(* Logix 5000 project; controller AMCI_3601_AOP_AOI_Sample_RSLogix_V28 vendor 1 type 14 code 108 rev 28.11; software revision 28.00; part 3 of 4 *)

ADD_ON_INSTRUCTION AMCI_3601_AOP_Program_Blend_Move   (* revision 0.0 *)
// Revision note:
// 3/2020: Version 0 is the initial release
VAR_INPUT
   Status_Bits_MSW : INT; {required}
   Status_Bits_LSW : INT; {required}
        .9   // The 3601 module sets this bit to Acknowledge the receipt of a blend move programming block
   Number_of_Segments : INT; {required}
   Final_Move_Deceleration : INT; {required}
   Acceleration_Type_segments_9_to_16 : INT;
   Acceleration_Type_segments_1_to_8 : INT;
   Segment_1_Distance : DINT; {required}
   Segment_1_Programmed_Speed : DINT; {required}
   Segment_1_Acceleration_Deceleration : INT; {required}
   Segment_2_Distance : DINT; {required}
   Segment_2_Programmed_Speed : DINT; {required}
   Segment_2_Acceleration_Deceleration : INT; {required}
   Segment_3_Distance : DINT; {required}
   Segment_3_Programmed_Speed : DINT; {required}
   Segment_3_Acceleration_Deceleration : INT; {required}
   Segment_4_Distance : DINT; {required}
   Segment_4_Programmed_Speed : DINT; {required}
   Segment_4_Acceleration_Deceleration : INT; {required}
   Segment_5_Distance : DINT; {required}
   Segment_5_Programmed_Speed : DINT; {required}
   Segment_5_Acceleration_Deceleration : INT; {required}
   Segment_6_Distance : DINT; {required}
   Segment_6_Programmed_Speed : DINT; {required}
   Segment_6_Acceleration_Deceleration : INT; {required}
   Segment_7_Distance : DINT; {required}
   Segment_7_Programmed_Speed : DINT; {required}
   Segment_7_Acceleration_Deceleration : INT; {required}
   Segment_8_Distance : DINT; {required}
   Segment_8_Programmed_Speed : DINT; {required}
   Segment_8_Acceleration_Deceleration : INT; {required}
   Segment_9_Distance : DINT; {required}
   Segment_9_Programmed_Speed : DINT; {required}
   Segment_9_Acceleration_Deceleration : INT; {required}
   Segment_10_Distance : DINT; {required}
   Segment_10_Programmed_Speed : DINT; {required}
   Segment_10_Acceleration_Deceleration : INT; {required}
   Segment_11_Distance : DINT; {required}
   Segment_11_Programmed_Speed : DINT; {required}
   Segment_11_Acceleration_Deceleration : INT; {required}
   Segment_12_Distance : DINT; {required}
   Segment_12_Programmed_Speed : DINT; {required}
   Segment_12_Acceleration_Deceleration : INT; {required}
   Segment_13_Distance : DINT; {required}
   Segment_13_Programmed_Speed : DINT; {required}
   Segment_13_Acceleration_Deceleration : INT; {required}
   Segment_14_Distance : DINT; {required}
   Segment_14_Programmed_Speed : DINT; {required}
   Segment_14_Acceleration_Deceleration : INT; {required}
   Segment_15_Distance : DINT; {required}
   Segment_15_Programmed_Speed : DINT; {required}
   Segment_15_Acceleration_Deceleration : INT; {required}
   Segment_16_Distance : DINT; {required}
   Segment_16_Programmed_Speed : DINT; {required}
   Segment_16_Acceleration_Deceleration : INT; {required}
END_VAR
VAR_OUTPUT
   Blend_Move_Programmed : BOOL; {access Read Only, visible}
END_VAR
VAR_IN_OUT
   AMCI_3601_output_data : AM:1769_3601:O:0; {required}
END_VAR
VAR
   command_data_block : INT[8];
   Blend_Move_setup : INT[8] := ([1] := 768);
   Blend_Move_counter : COUNTER;
   Programmed_Speed : DINT;
   Distance : DINT;
   upper_result_X_1000 : DINT;
END_VAR

ROUTINE Logic   (* ladder *)
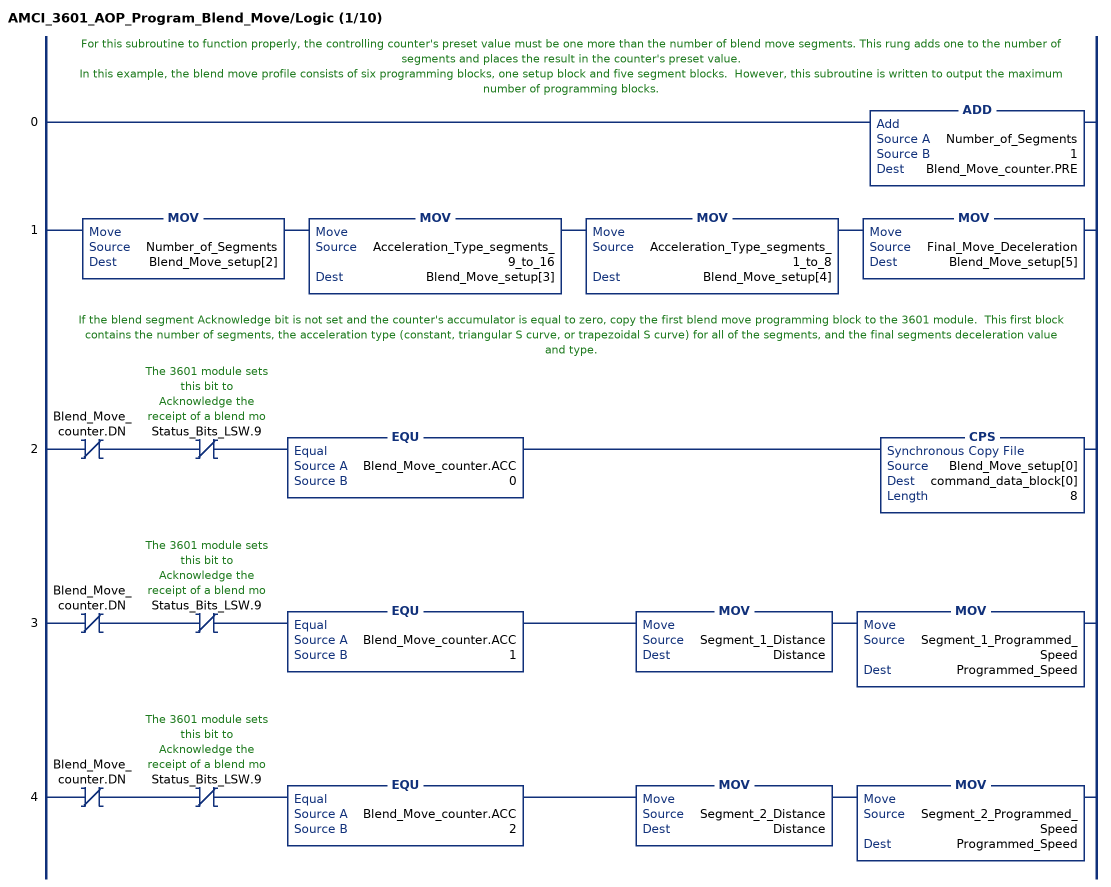
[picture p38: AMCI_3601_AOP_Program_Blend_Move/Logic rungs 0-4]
   // For this subroutine to function properly, the controlling counter's preset value must be one more than the number of blend move segments. This rung adds one to the number of segments and places the result in the counter's preset value.
   // In this example, the blend move profile consists of six programming blocks, one setup block and five segment blocks.  However, this subroutine is written to output the maximum number of programming blocks.
   0: ADD(Number_of_Segments,1,Blend_Move_counter.PRE);
   1: MOV(Number_of_Segments,Blend_Move_setup[2])MOV(Acceleration_Type_segments_9_to_16,Blend_Move_setup[3])MOV(Acceleration_Type_segments_1_to_8,Blend_Move_setup[4])MOV(Final_Move_Deceleration,Blend_Move_setup[5]);
   // If the blend segment Acknowledge bit is not set and the counter's accumulator is equal to zero, copy the first blend move programming block to the 3601 module.  This first block contains the number of segments, the acceleration type (constant, triangular S curve, or trapezoidal S curve) for all of the segments, and the final segments deceleration value and type.
   2: XIO(Blend_Move_counter.DN)XIO(Status_Bits_LSW.9)EQU(Blend_Move_counter.ACC,0)CPS(Blend_Move_setup[0],command_data_block[0],8);
   3: XIO(Blend_Move_counter.DN)XIO(Status_Bits_LSW.9)EQU(Blend_Move_counter.ACC,1)MOV(Segment_1_Distance,Distance)MOV(Segment_1_Programmed_Speed,Programmed_Speed);
   4: XIO(Blend_Move_counter.DN)XIO(Status_Bits_LSW.9)EQU(Blend_Move_counter.ACC,2)MOV(Segment_2_Distance,Distance)MOV(Segment_2_Programmed_Speed,Programmed_Speed);
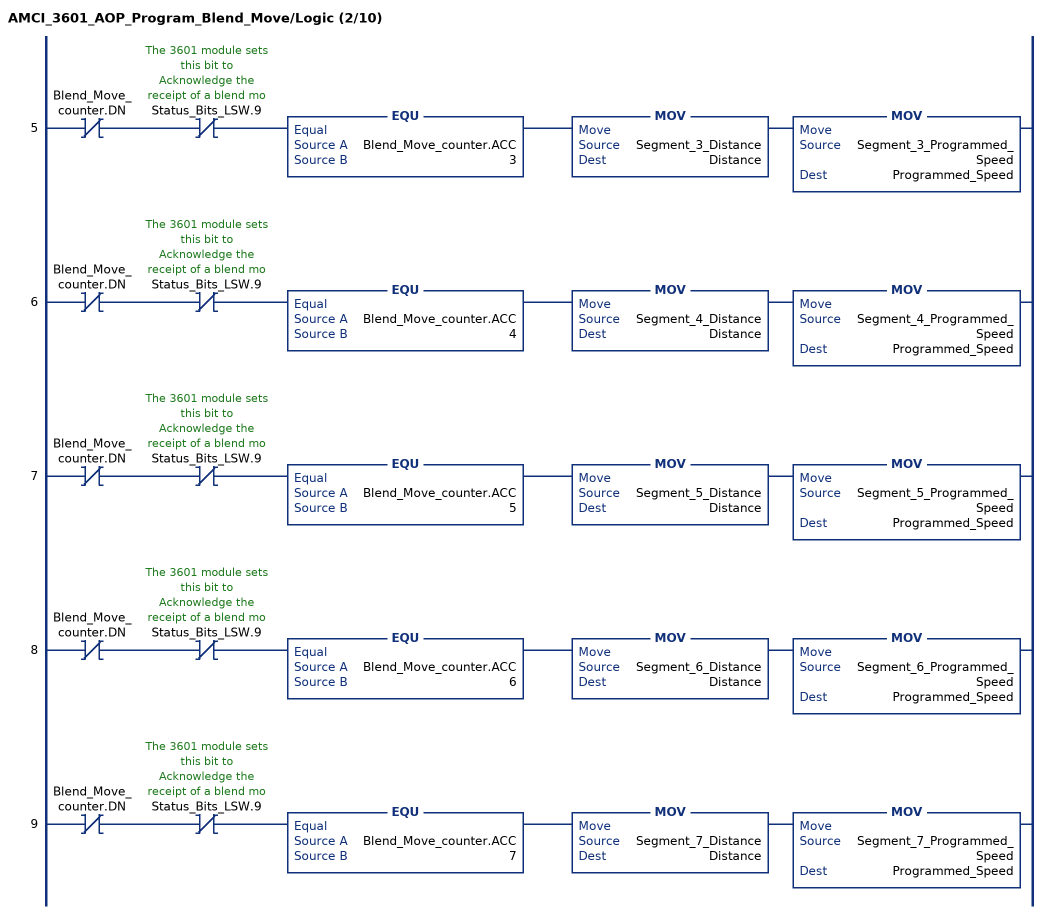
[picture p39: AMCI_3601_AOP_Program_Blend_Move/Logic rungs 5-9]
   5: XIO(Blend_Move_counter.DN)XIO(Status_Bits_LSW.9)EQU(Blend_Move_counter.ACC,3)MOV(Segment_3_Distance,Distance)MOV(Segment_3_Programmed_Speed,Programmed_Speed);
   6: XIO(Blend_Move_counter.DN)XIO(Status_Bits_LSW.9)EQU(Blend_Move_counter.ACC,4)MOV(Segment_4_Distance,Distance)MOV(Segment_4_Programmed_Speed,Programmed_Speed);
   7: XIO(Blend_Move_counter.DN)XIO(Status_Bits_LSW.9)EQU(Blend_Move_counter.ACC,5)MOV(Segment_5_Distance,Distance)MOV(Segment_5_Programmed_Speed,Programmed_Speed);
   8: XIO(Blend_Move_counter.DN)XIO(Status_Bits_LSW.9)EQU(Blend_Move_counter.ACC,6)MOV(Segment_6_Distance,Distance)MOV(Segment_6_Programmed_Speed,Programmed_Speed);
   9: XIO(Blend_Move_counter.DN)XIO(Status_Bits_LSW.9)EQU(Blend_Move_counter.ACC,7)MOV(Segment_7_Distance,Distance)MOV(Segment_7_Programmed_Speed,Programmed_Speed);
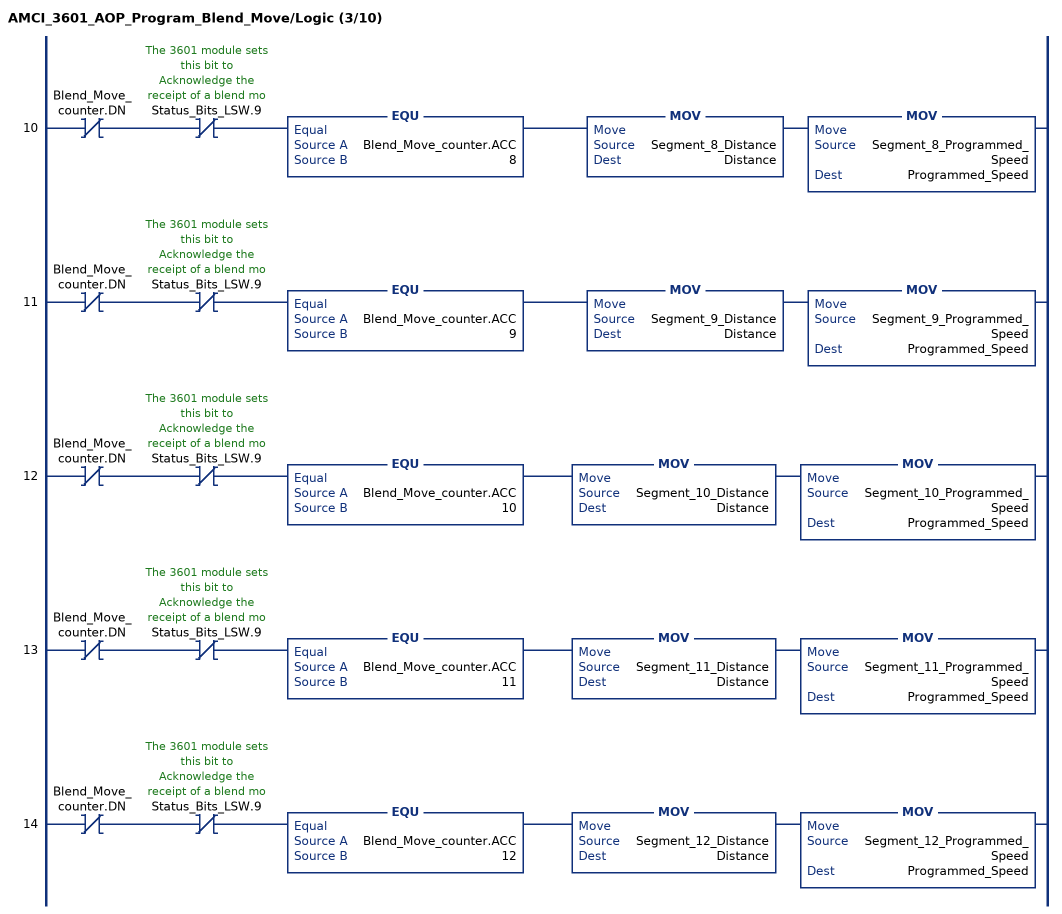
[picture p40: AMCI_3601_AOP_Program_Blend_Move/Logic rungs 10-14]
   10: XIO(Blend_Move_counter.DN)XIO(Status_Bits_LSW.9)EQU(Blend_Move_counter.ACC,8)MOV(Segment_8_Distance,Distance)MOV(Segment_8_Programmed_Speed,Programmed_Speed);
   11: XIO(Blend_Move_counter.DN)XIO(Status_Bits_LSW.9)EQU(Blend_Move_counter.ACC,9)MOV(Segment_9_Distance,Distance)MOV(Segment_9_Programmed_Speed,Programmed_Speed);
   12: XIO(Blend_Move_counter.DN)XIO(Status_Bits_LSW.9)EQU(Blend_Move_counter.ACC,10)MOV(Segment_10_Distance,Distance)MOV(Segment_10_Programmed_Speed,Programmed_Speed);
   13: XIO(Blend_Move_counter.DN)XIO(Status_Bits_LSW.9)EQU(Blend_Move_counter.ACC,11)MOV(Segment_11_Distance,Distance)MOV(Segment_11_Programmed_Speed,Programmed_Speed);
   14: XIO(Blend_Move_counter.DN)XIO(Status_Bits_LSW.9)EQU(Blend_Move_counter.ACC,12)MOV(Segment_12_Distance,Distance)MOV(Segment_12_Programmed_Speed,Programmed_Speed);
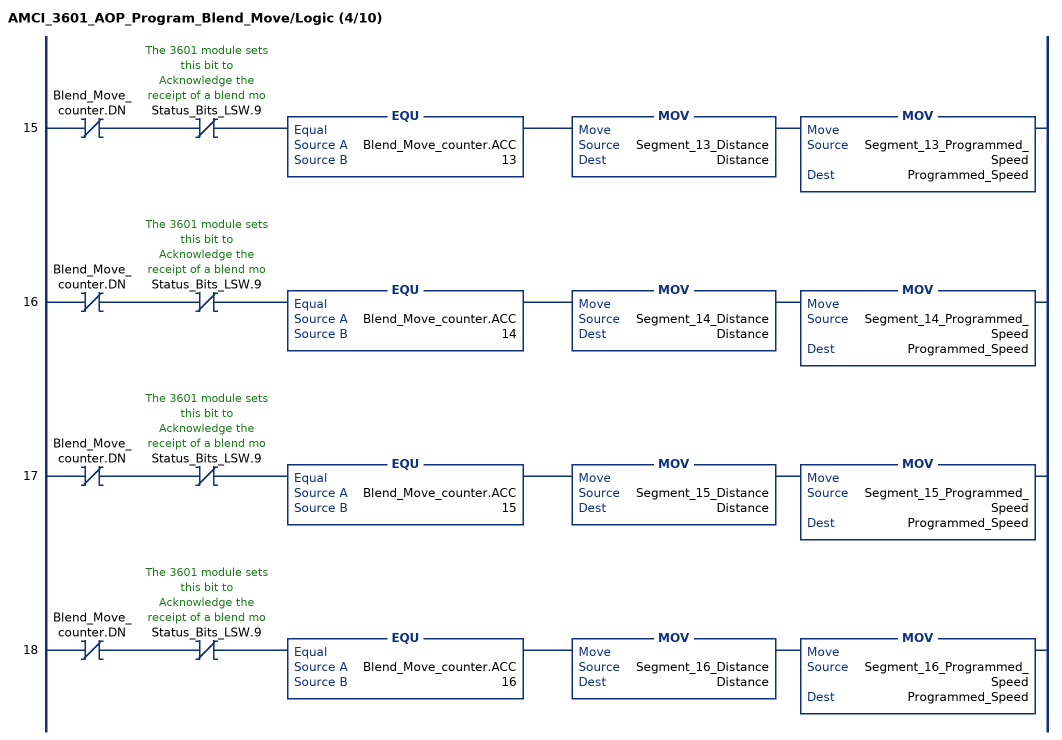
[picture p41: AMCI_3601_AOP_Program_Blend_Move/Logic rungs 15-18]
   15: XIO(Blend_Move_counter.DN)XIO(Status_Bits_LSW.9)EQU(Blend_Move_counter.ACC,13)MOV(Segment_13_Distance,Distance)MOV(Segment_13_Programmed_Speed,Programmed_Speed);
   16: XIO(Blend_Move_counter.DN)XIO(Status_Bits_LSW.9)EQU(Blend_Move_counter.ACC,14)MOV(Segment_14_Distance,Distance)MOV(Segment_14_Programmed_Speed,Programmed_Speed);
   17: XIO(Blend_Move_counter.DN)XIO(Status_Bits_LSW.9)EQU(Blend_Move_counter.ACC,15)MOV(Segment_15_Distance,Distance)MOV(Segment_15_Programmed_Speed,Programmed_Speed);
   18: XIO(Blend_Move_counter.DN)XIO(Status_Bits_LSW.9)EQU(Blend_Move_counter.ACC,16)MOV(Segment_16_Distance,Distance)MOV(Segment_16_Programmed_Speed,Programmed_Speed);
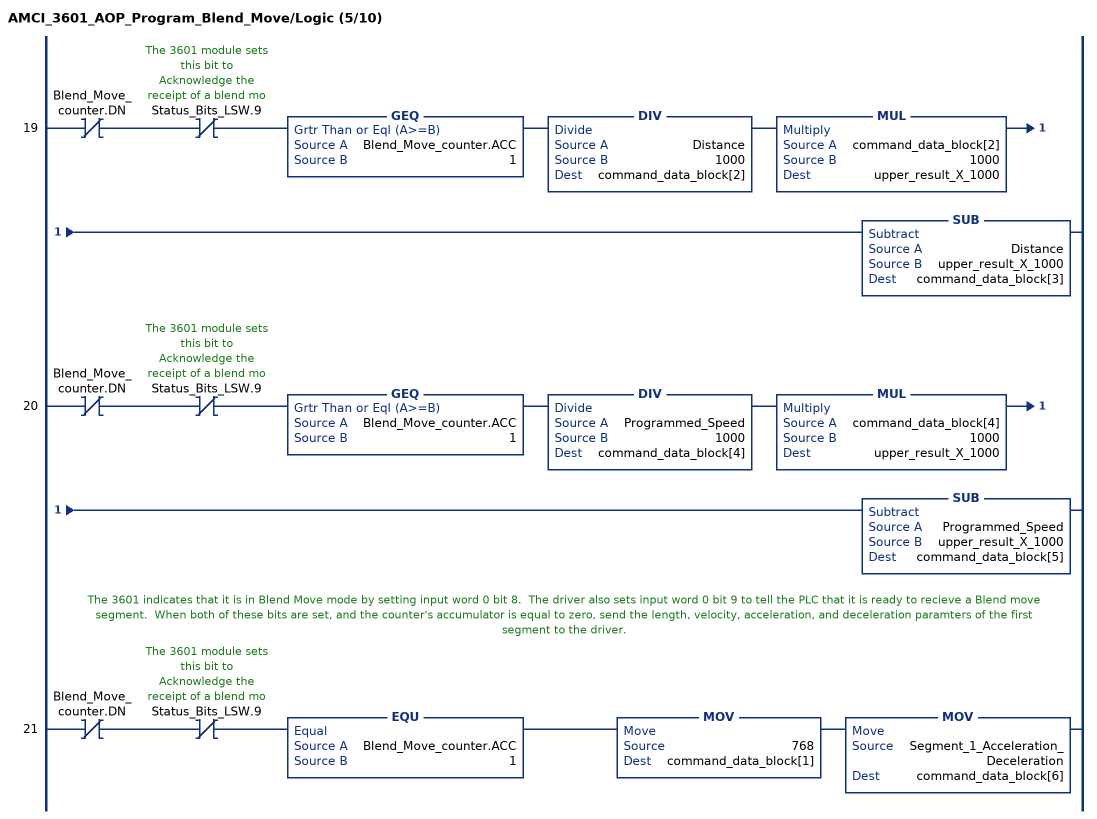
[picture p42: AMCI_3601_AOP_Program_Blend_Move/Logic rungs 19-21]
   19: XIO(Blend_Move_counter.DN)XIO(Status_Bits_LSW.9)GEQ(Blend_Move_counter.ACC,1)DIV(Distance,1000,command_data_block[2])MUL(command_data_block[2],1000,upper_result_X_1000)SUB(Distance,upper_result_X_1000,command_data_block[3]);
   20: XIO(Blend_Move_counter.DN)XIO(Status_Bits_LSW.9)GEQ(Blend_Move_counter.ACC,1)DIV(Programmed_Speed,1000,command_data_block[4])MUL(command_data_block[4],1000,upper_result_X_1000)SUB(Programmed_Speed,upper_result_X_1000,command_data_block[5]);
   // The 3601 indicates that it is in Blend Move mode by setting input word 0 bit 8.  The driver also sets input word 0 bit 9 to tell the PLC that it is ready to recieve a Blend move segment.  When both of these bits are set, and the counter's accumulator is equal to zero, send the length, velocity, acceleration, and deceleration paramters of the first segment to the driver.
   21: XIO(Blend_Move_counter.DN)XIO(Status_Bits_LSW.9)EQU(Blend_Move_counter.ACC,1)MOV(768,command_data_block[1])MOV(Segment_1_Acceleration_Deceleration,command_data_block[6]);
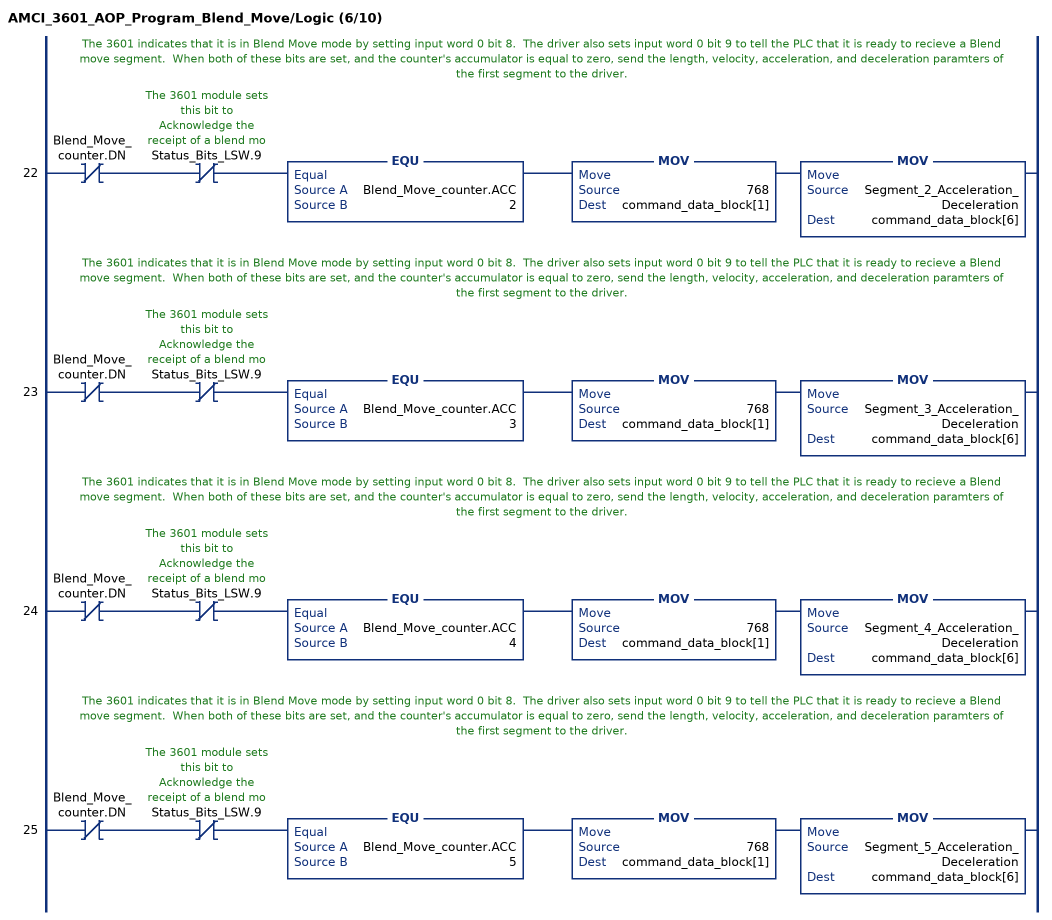
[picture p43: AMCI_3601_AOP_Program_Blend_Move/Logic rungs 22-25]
   // The 3601 indicates that it is in Blend Move mode by setting input word 0 bit 8.  The driver also sets input word 0 bit 9 to tell the PLC that it is ready to recieve a Blend move segment.  When both of these bits are set, and the counter's accumulator is equal to zero, send the length, velocity, acceleration, and deceleration paramters of the first segment to the driver.
   22: XIO(Blend_Move_counter.DN)XIO(Status_Bits_LSW.9)EQU(Blend_Move_counter.ACC,2)MOV(768,command_data_block[1])MOV(Segment_2_Acceleration_Deceleration,command_data_block[6]);
   // The 3601 indicates that it is in Blend Move mode by setting input word 0 bit 8.  The driver also sets input word 0 bit 9 to tell the PLC that it is ready to recieve a Blend move segment.  When both of these bits are set, and the counter's accumulator is equal to zero, send the length, velocity, acceleration, and deceleration paramters of the first segment to the driver.
   23: XIO(Blend_Move_counter.DN)XIO(Status_Bits_LSW.9)EQU(Blend_Move_counter.ACC,3)MOV(768,command_data_block[1])MOV(Segment_3_Acceleration_Deceleration,command_data_block[6]);
   // The 3601 indicates that it is in Blend Move mode by setting input word 0 bit 8.  The driver also sets input word 0 bit 9 to tell the PLC that it is ready to recieve a Blend move segment.  When both of these bits are set, and the counter's accumulator is equal to zero, send the length, velocity, acceleration, and deceleration paramters of the first segment to the driver.
   24: XIO(Blend_Move_counter.DN)XIO(Status_Bits_LSW.9)EQU(Blend_Move_counter.ACC,4)MOV(768,command_data_block[1])MOV(Segment_4_Acceleration_Deceleration,command_data_block[6]);
   // The 3601 indicates that it is in Blend Move mode by setting input word 0 bit 8.  The driver also sets input word 0 bit 9 to tell the PLC that it is ready to recieve a Blend move segment.  When both of these bits are set, and the counter's accumulator is equal to zero, send the length, velocity, acceleration, and deceleration paramters of the first segment to the driver.
   25: XIO(Blend_Move_counter.DN)XIO(Status_Bits_LSW.9)EQU(Blend_Move_counter.ACC,5)MOV(768,command_data_block[1])MOV(Segment_5_Acceleration_Deceleration,command_data_block[6]);
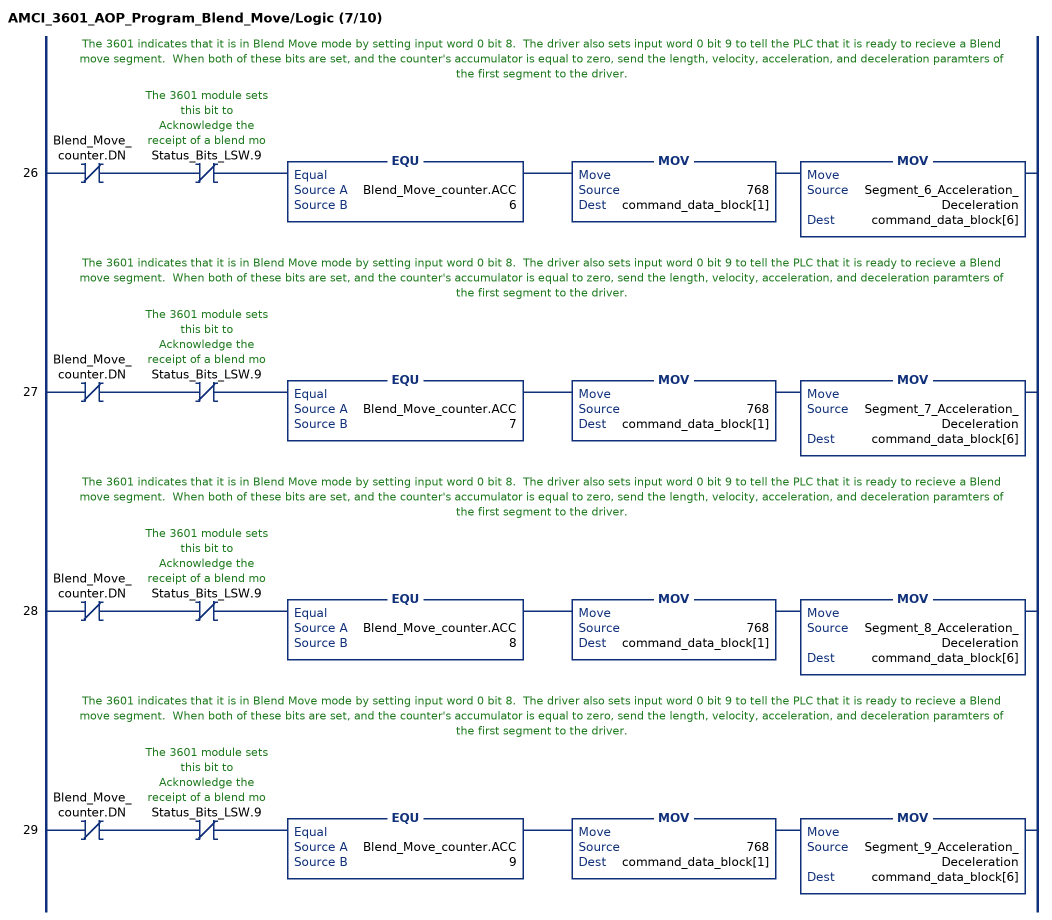
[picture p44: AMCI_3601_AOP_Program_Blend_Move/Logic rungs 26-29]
   // The 3601 indicates that it is in Blend Move mode by setting input word 0 bit 8.  The driver also sets input word 0 bit 9 to tell the PLC that it is ready to recieve a Blend move segment.  When both of these bits are set, and the counter's accumulator is equal to zero, send the length, velocity, acceleration, and deceleration paramters of the first segment to the driver.
   26: XIO(Blend_Move_counter.DN)XIO(Status_Bits_LSW.9)EQU(Blend_Move_counter.ACC,6)MOV(768,command_data_block[1])MOV(Segment_6_Acceleration_Deceleration,command_data_block[6]);
   // The 3601 indicates that it is in Blend Move mode by setting input word 0 bit 8.  The driver also sets input word 0 bit 9 to tell the PLC that it is ready to recieve a Blend move segment.  When both of these bits are set, and the counter's accumulator is equal to zero, send the length, velocity, acceleration, and deceleration paramters of the first segment to the driver.
   27: XIO(Blend_Move_counter.DN)XIO(Status_Bits_LSW.9)EQU(Blend_Move_counter.ACC,7)MOV(768,command_data_block[1])MOV(Segment_7_Acceleration_Deceleration,command_data_block[6]);
   // The 3601 indicates that it is in Blend Move mode by setting input word 0 bit 8.  The driver also sets input word 0 bit 9 to tell the PLC that it is ready to recieve a Blend move segment.  When both of these bits are set, and the counter's accumulator is equal to zero, send the length, velocity, acceleration, and deceleration paramters of the first segment to the driver.
   28: XIO(Blend_Move_counter.DN)XIO(Status_Bits_LSW.9)EQU(Blend_Move_counter.ACC,8)MOV(768,command_data_block[1])MOV(Segment_8_Acceleration_Deceleration,command_data_block[6]);
   // The 3601 indicates that it is in Blend Move mode by setting input word 0 bit 8.  The driver also sets input word 0 bit 9 to tell the PLC that it is ready to recieve a Blend move segment.  When both of these bits are set, and the counter's accumulator is equal to zero, send the length, velocity, acceleration, and deceleration paramters of the first segment to the driver.
   29: XIO(Blend_Move_counter.DN)XIO(Status_Bits_LSW.9)EQU(Blend_Move_counter.ACC,9)MOV(768,command_data_block[1])MOV(Segment_9_Acceleration_Deceleration,command_data_block[6]);
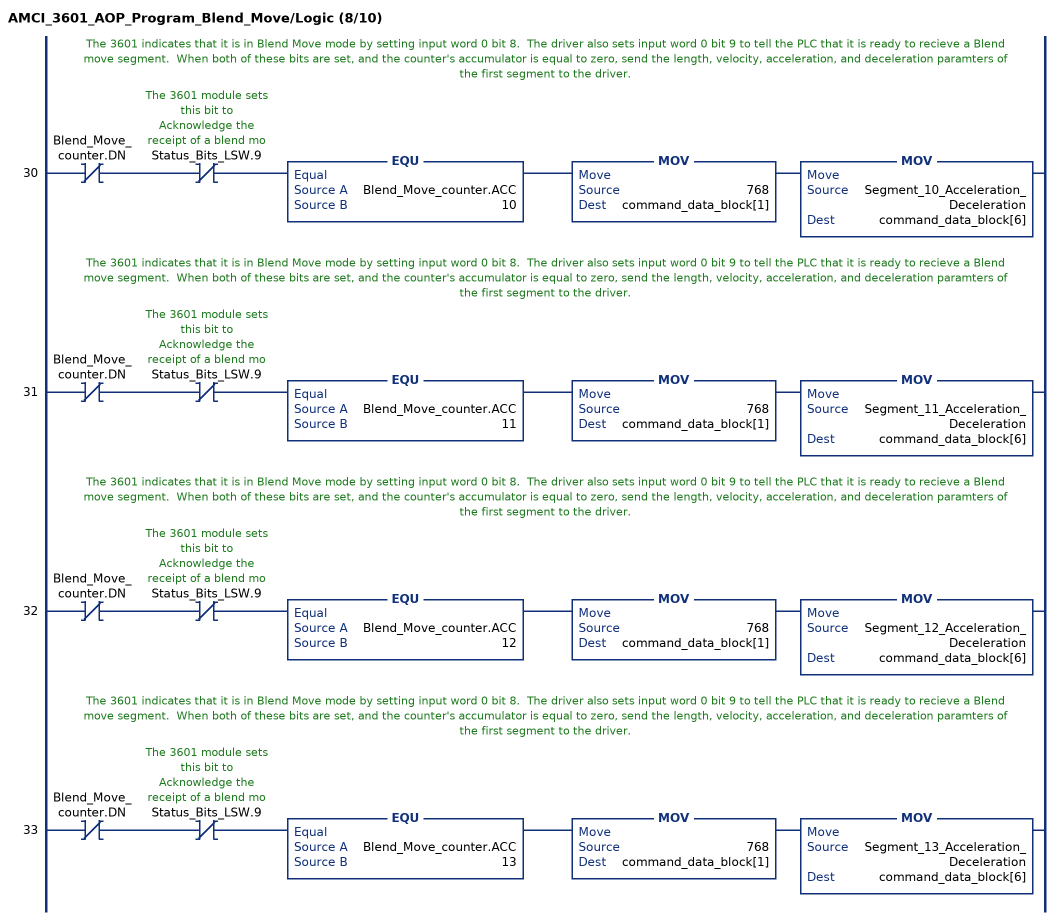
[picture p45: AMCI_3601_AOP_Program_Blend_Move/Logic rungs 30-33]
   // The 3601 indicates that it is in Blend Move mode by setting input word 0 bit 8.  The driver also sets input word 0 bit 9 to tell the PLC that it is ready to recieve a Blend move segment.  When both of these bits are set, and the counter's accumulator is equal to zero, send the length, velocity, acceleration, and deceleration paramters of the first segment to the driver.
   30: XIO(Blend_Move_counter.DN)XIO(Status_Bits_LSW.9)EQU(Blend_Move_counter.ACC,10)MOV(768,command_data_block[1])MOV(Segment_10_Acceleration_Deceleration,command_data_block[6]);
   // The 3601 indicates that it is in Blend Move mode by setting input word 0 bit 8.  The driver also sets input word 0 bit 9 to tell the PLC that it is ready to recieve a Blend move segment.  When both of these bits are set, and the counter's accumulator is equal to zero, send the length, velocity, acceleration, and deceleration paramters of the first segment to the driver.
   31: XIO(Blend_Move_counter.DN)XIO(Status_Bits_LSW.9)EQU(Blend_Move_counter.ACC,11)MOV(768,command_data_block[1])MOV(Segment_11_Acceleration_Deceleration,command_data_block[6]);
   // The 3601 indicates that it is in Blend Move mode by setting input word 0 bit 8.  The driver also sets input word 0 bit 9 to tell the PLC that it is ready to recieve a Blend move segment.  When both of these bits are set, and the counter's accumulator is equal to zero, send the length, velocity, acceleration, and deceleration paramters of the first segment to the driver.
   32: XIO(Blend_Move_counter.DN)XIO(Status_Bits_LSW.9)EQU(Blend_Move_counter.ACC,12)MOV(768,command_data_block[1])MOV(Segment_12_Acceleration_Deceleration,command_data_block[6]);
   // The 3601 indicates that it is in Blend Move mode by setting input word 0 bit 8.  The driver also sets input word 0 bit 9 to tell the PLC that it is ready to recieve a Blend move segment.  When both of these bits are set, and the counter's accumulator is equal to zero, send the length, velocity, acceleration, and deceleration paramters of the first segment to the driver.
   33: XIO(Blend_Move_counter.DN)XIO(Status_Bits_LSW.9)EQU(Blend_Move_counter.ACC,13)MOV(768,command_data_block[1])MOV(Segment_13_Acceleration_Deceleration,command_data_block[6]);
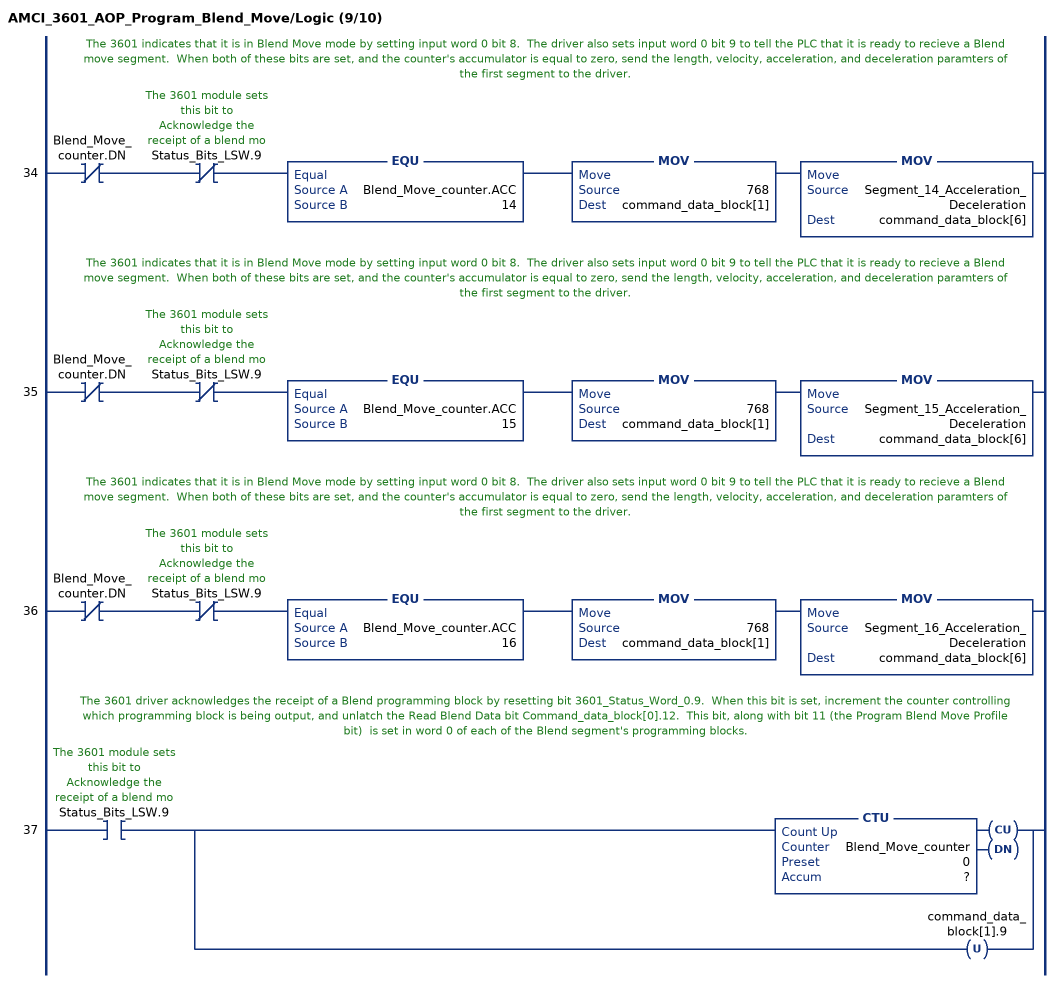
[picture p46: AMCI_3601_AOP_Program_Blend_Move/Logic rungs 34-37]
   // The 3601 indicates that it is in Blend Move mode by setting input word 0 bit 8.  The driver also sets input word 0 bit 9 to tell the PLC that it is ready to recieve a Blend move segment.  When both of these bits are set, and the counter's accumulator is equal to zero, send the length, velocity, acceleration, and deceleration paramters of the first segment to the driver.
   34: XIO(Blend_Move_counter.DN)XIO(Status_Bits_LSW.9)EQU(Blend_Move_counter.ACC,14)MOV(768,command_data_block[1])MOV(Segment_14_Acceleration_Deceleration,command_data_block[6]);
   // The 3601 indicates that it is in Blend Move mode by setting input word 0 bit 8.  The driver also sets input word 0 bit 9 to tell the PLC that it is ready to recieve a Blend move segment.  When both of these bits are set, and the counter's accumulator is equal to zero, send the length, velocity, acceleration, and deceleration paramters of the first segment to the driver.
   35: XIO(Blend_Move_counter.DN)XIO(Status_Bits_LSW.9)EQU(Blend_Move_counter.ACC,15)MOV(768,command_data_block[1])MOV(Segment_15_Acceleration_Deceleration,command_data_block[6]);
   // The 3601 indicates that it is in Blend Move mode by setting input word 0 bit 8.  The driver also sets input word 0 bit 9 to tell the PLC that it is ready to recieve a Blend move segment.  When both of these bits are set, and the counter's accumulator is equal to zero, send the length, velocity, acceleration, and deceleration paramters of the first segment to the driver.
   36: XIO(Blend_Move_counter.DN)XIO(Status_Bits_LSW.9)EQU(Blend_Move_counter.ACC,16)MOV(768,command_data_block[1])MOV(Segment_16_Acceleration_Deceleration,command_data_block[6]);
   // The 3601 driver acknowledges the receipt of a Blend programming block by resetting bit 3601_Status_Word_0.9.  When this bit is set, increment the counter controlling which programming block is being output, and unlatch the Read Blend Data bit Command_data_block[0].12.  This bit, along with bit 11 (the Program Blend Move Profile bit)  is set in word 0 of each of the Blend segment's programming blocks.
   37: XIC(Status_Bits_LSW.9)[CTU(Blend_Move_counter,?,?) ,OTU(command_data_block[1].9) ];
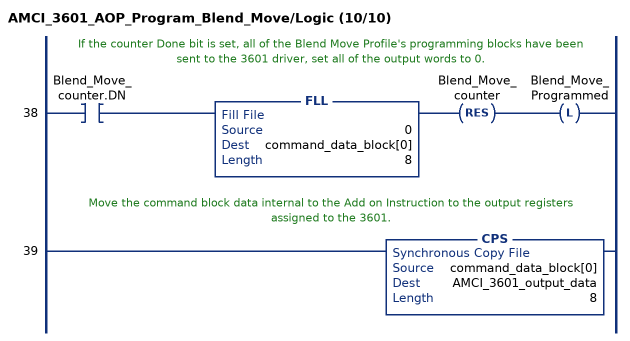
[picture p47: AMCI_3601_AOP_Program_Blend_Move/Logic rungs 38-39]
   // If the counter Done bit is set, all of the Blend Move Profile's programming blocks have been sent to the 3601 driver, set all of the output words to 0.
   38: XIC(Blend_Move_counter.DN)FLL(0,command_data_block[0],8)RES(Blend_Move_counter)OTL(Blend_Move_Programmed);
   // Move the command block data internal to the Add on Instruction to the output registers assigned to the 3601.
   39: CPS(command_data_block[0],AMCI_3601_output_data,8);
END_ROUTINE
END_ADD_ON_INSTRUCTION

ADD_ON_INSTRUCTION AMCI_3601_AOP_Registration_CCW   (* revision 0.0, vendor AMCI, ExecuteEnableInFalse *)
// Revision note:
// 3/2020: Version 0 is the initial release
VAR_INPUT
   Axis_Status_Bits : INT; {required}
   _0_normal_1_S_Curve_Acceleration : BOOL;
   _0_Triangular_1_Trapezoidal_S_Curve : BOOL;
   Target_Position : DINT; {required}
   Programmed_Speed : DINT; {required}
   Acceleration : INT; {required}
   Deceleration : INT; {required}
END_VAR
VAR_OUTPUT
   EN : BOOL; {access Read Only, visible}
   Registration_Move_CCW_Occurring : BOOL; {access Read Only, visible}
   ER : BOOL; {access Read Only, visible}
END_VAR
VAR_IN_OUT
   AMCI_3601_output_data : AM:1769_3601:O:0; {required}
END_VAR
VAR
   Upper_Result_X_1000 : DINT;
   command_data_block : INT[10];
        [1]   // Command Bits LSW
        [3]   // Lower Target Position
        [5]   // Lower Programmed Speed
        [0]   // Command Bits MSW
        [2]   // Upper Target Position
        [4]   // Upper Programmed Speed
END_VAR

ROUTINE EnableInFalse   (* ladder *)
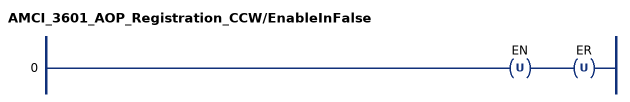
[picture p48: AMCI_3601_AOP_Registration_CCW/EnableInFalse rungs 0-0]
   0: OTU(EN)OTU(ER);
END_ROUTINE

ROUTINE Logic   (* ladder *)
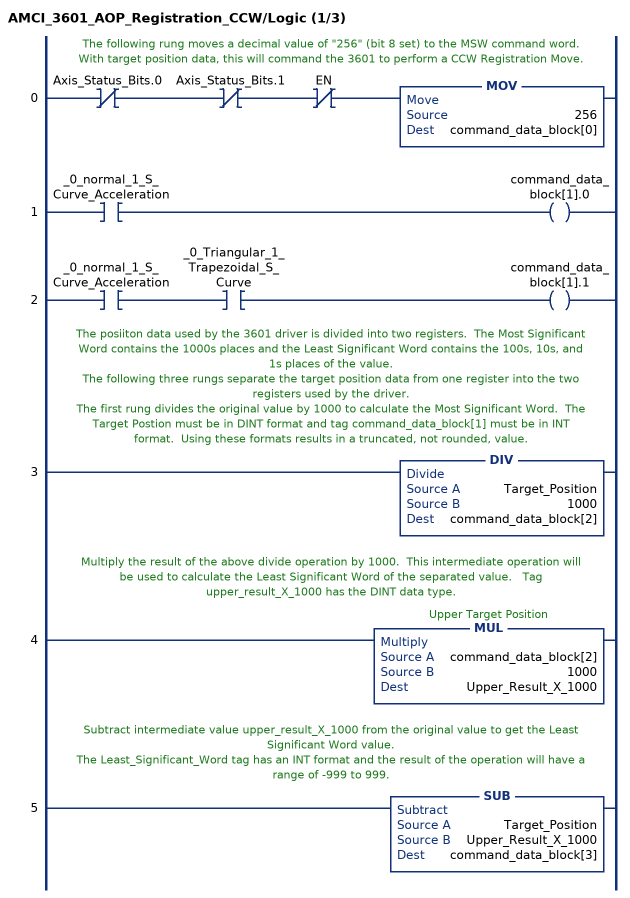
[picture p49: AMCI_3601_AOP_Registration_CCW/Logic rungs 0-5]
   // The following rung moves a decimal value of "256" (bit 8 set) to the MSW command word.  With target position data, this will command the 3601 to perform a CCW Registration Move.
   0: XIO(Axis_Status_Bits.0)XIO(Axis_Status_Bits.1)XIO(EN)MOV(256,command_data_block[0]);
   1: XIC(_0_normal_1_S_Curve_Acceleration)OTE(command_data_block[1].0);
   2: XIC(_0_normal_1_S_Curve_Acceleration)XIC(_0_Triangular_1_Trapezoidal_S_Curve)OTE(command_data_block[1].1);
   // The posiiton data used by the 3601 driver is divided into two registers.  The Most Significant Word contains the 1000s places and the Least Significant Word contains the 100s, 10s, and 1s places of the value.
   // The following three rungs separate the target position data from one register into the two registers used by the driver.
   // The first rung divides the original value by 1000 to calculate the Most Significant Word.  The Target Postion must be in DINT format and tag command_data_block[1] must be in INT format.  Using these formats results in a truncated, not rounded, value.
   3: DIV(Target_Position,1000,command_data_block[2]);
   // Multiply the result of the above divide operation by 1000.  This intermediate operation will be used to calculate the Least Significant Word of the separated value.   Tag upper_result_X_1000 has the DINT data type.
   4: MUL(command_data_block[2],1000,Upper_Result_X_1000);
   // Subtract intermediate value upper_result_X_1000 from the original value to get the Least Significant Word value.
   // The Least_Significant_Word tag has an INT format and the result of the operation will have a range of -999 to 999.
   5: SUB(Target_Position,Upper_Result_X_1000,command_data_block[3]);
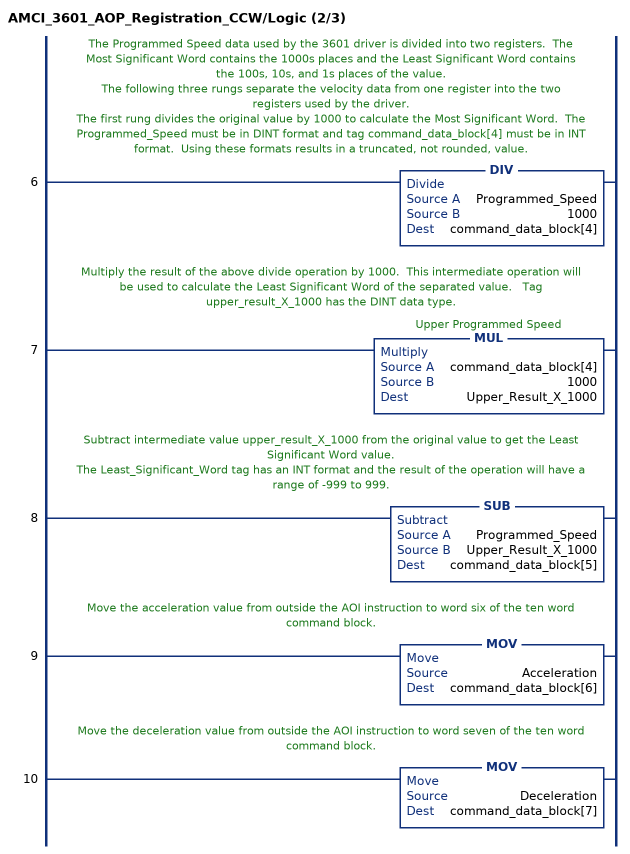
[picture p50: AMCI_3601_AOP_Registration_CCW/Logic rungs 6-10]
   // The Programmed Speed data used by the 3601 driver is divided into two registers.  The Most Significant Word contains the 1000s places and the Least Significant Word contains the 100s, 10s, and 1s places of the value.
   // The following three rungs separate the velocity data from one register into the two registers used by the driver.
   // The first rung divides the original value by 1000 to calculate the Most Significant Word.  The Programmed_Speed must be in DINT format and tag command_data_block[4] must be in INT format.  Using these formats results in a truncated, not rounded, value.
   6: DIV(Programmed_Speed,1000,command_data_block[4]);
   // Multiply the result of the above divide operation by 1000.  This intermediate operation will be used to calculate the Least Significant Word of the separated value.   Tag upper_result_X_1000 has the DINT data type.
   7: MUL(command_data_block[4],1000,Upper_Result_X_1000);
   // Subtract intermediate value upper_result_X_1000 from the original value to get the Least Significant Word value.
   // The Least_Significant_Word tag has an INT format and the result of the operation will have a range of -999 to 999.
   8: SUB(Programmed_Speed,Upper_Result_X_1000,command_data_block[5]);
   // Move the acceleration value from outside the AOI instruction to word six of the ten word command block.
   9: MOV(Acceleration,command_data_block[6]);
   // Move the deceleration value from outside the AOI instruction to word seven of the ten word command block.
   10: MOV(Deceleration,command_data_block[7]);
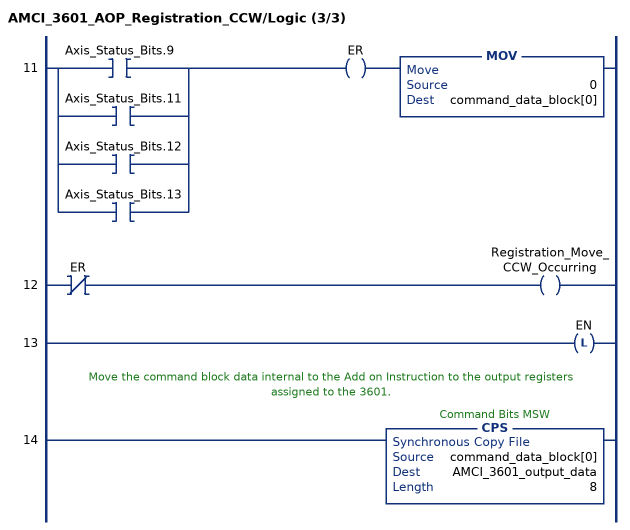
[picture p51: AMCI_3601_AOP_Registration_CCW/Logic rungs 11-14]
   11: [XIC(Axis_Status_Bits.9) ,XIC(Axis_Status_Bits.11) ,XIC(Axis_Status_Bits.12) ,XIC(Axis_Status_Bits.13) ]OTE(ER)MOV(0,command_data_block[0]);
   12: XIO(ER)OTE(Registration_Move_CCW_Occurring);
   13: OTL(EN);
   // Move the command block data internal to the Add on Instruction to the output registers assigned to the 3601.
   14: CPS(command_data_block[0],AMCI_3601_output_data,8);
END_ROUTINE
END_ADD_ON_INSTRUCTION

ADD_ON_INSTRUCTION AMCI_3601_AOP_Registration_CW   (* revision 0.0, vendor AMCI, ExecuteEnableInFalse *)
// Revision note:
// 3/2020: Version 0 is the initial release
VAR_INPUT
   Axis_Status_Bits : INT; {required}
   _0_normal_1_S_Curve_Acceleration : BOOL;
   _0_Triangular_1_Trapezoidal_S_Curve : BOOL;
   Target_Position : DINT; {required}
   Programmed_Speed : DINT; {required}
   Acceleration : INT; {required}
   Deceleration : INT; {required}
END_VAR
VAR_OUTPUT
   EN : BOOL; {access Read Only, visible}
   Registration_Move_CW_Occurring : BOOL; {access Read Only, visible}
   ER : BOOL; {access Read Only, visible}
END_VAR
VAR_IN_OUT
   AMCI_3601_output_data : AM:1769_3601:O:0; {required}
END_VAR
VAR
   Upper_Result_X_1000 : DINT;
   command_data_block : INT[10];
        [1]   // Command Bits LSW
        [3]   // Lower Target Position
        [5]   // Lower Programmed Speed
        [0]   // Command Bits MSW
        [2]   // Upper Target Position
        [4]   // Upper Programmed Speed
END_VAR

ROUTINE EnableInFalse   (* ladder *)
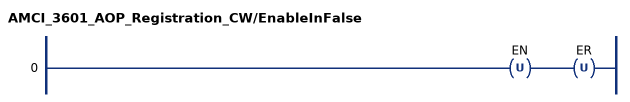
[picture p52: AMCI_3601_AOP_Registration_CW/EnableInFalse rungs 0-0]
   0: OTU(EN)OTU(ER);
END_ROUTINE

ROUTINE Logic   (* ladder *)
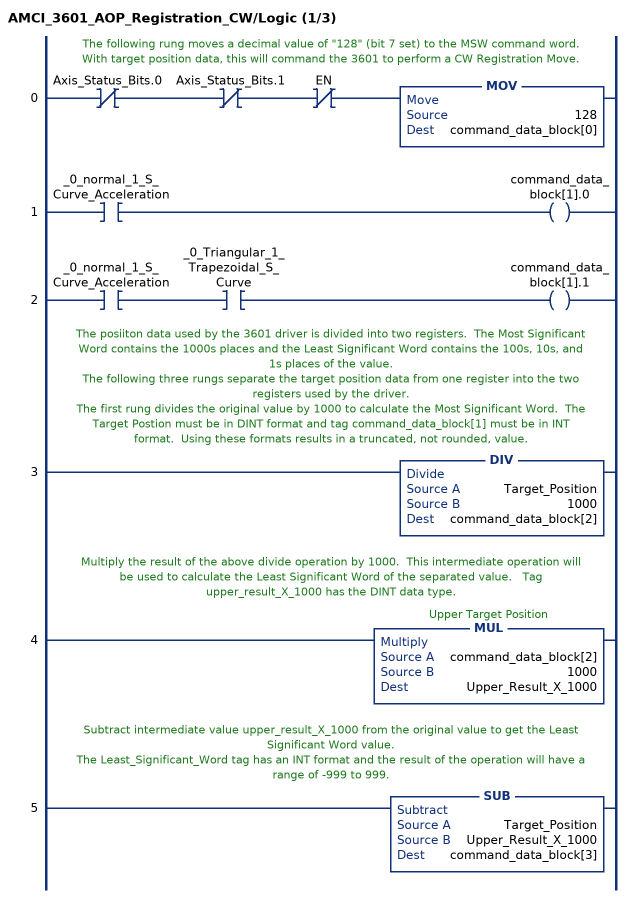
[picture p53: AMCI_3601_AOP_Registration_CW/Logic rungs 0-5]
   // The following rung moves a decimal value of "128" (bit 7 set) to the MSW command word.  With target position data, this will command the 3601 to perform a CW Registration Move.
   0: XIO(Axis_Status_Bits.0)XIO(Axis_Status_Bits.1)XIO(EN)MOV(128,command_data_block[0]);
   1: XIC(_0_normal_1_S_Curve_Acceleration)OTE(command_data_block[1].0);
   2: XIC(_0_normal_1_S_Curve_Acceleration)XIC(_0_Triangular_1_Trapezoidal_S_Curve)OTE(command_data_block[1].1);
   // The posiiton data used by the 3601 driver is divided into two registers.  The Most Significant Word contains the 1000s places and the Least Significant Word contains the 100s, 10s, and 1s places of the value.
   // The following three rungs separate the target position data from one register into the two registers used by the driver.
   // The first rung divides the original value by 1000 to calculate the Most Significant Word.  The Target Postion must be in DINT format and tag command_data_block[1] must be in INT format.  Using these formats results in a truncated, not rounded, value.
   3: DIV(Target_Position,1000,command_data_block[2]);
   // Multiply the result of the above divide operation by 1000.  This intermediate operation will be used to calculate the Least Significant Word of the separated value.   Tag upper_result_X_1000 has the DINT data type.
   4: MUL(command_data_block[2],1000,Upper_Result_X_1000);
   // Subtract intermediate value upper_result_X_1000 from the original value to get the Least Significant Word value.
   // The Least_Significant_Word tag has an INT format and the result of the operation will have a range of -999 to 999.
   5: SUB(Target_Position,Upper_Result_X_1000,command_data_block[3]);
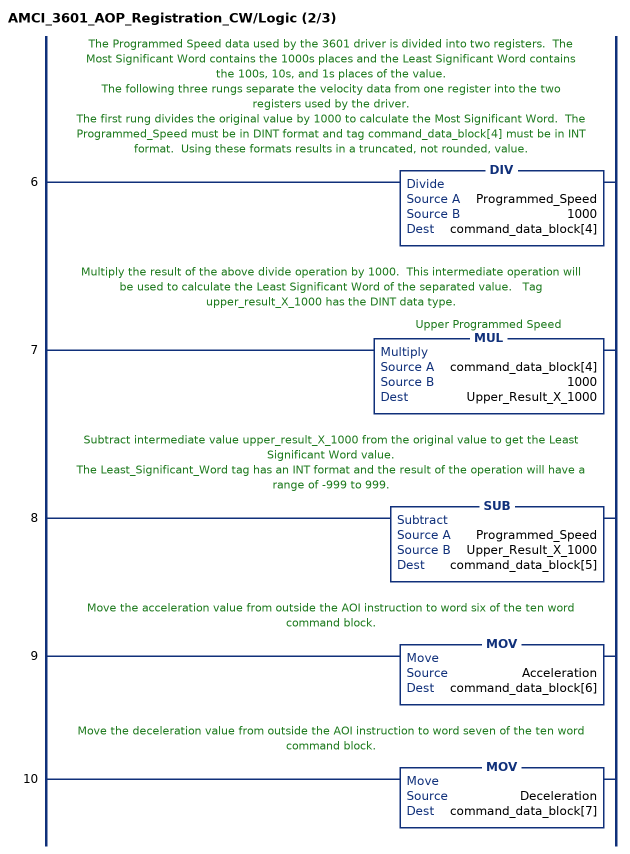
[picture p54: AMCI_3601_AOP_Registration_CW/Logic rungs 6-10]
   // The Programmed Speed data used by the 3601 driver is divided into two registers.  The Most Significant Word contains the 1000s places and the Least Significant Word contains the 100s, 10s, and 1s places of the value.
   // The following three rungs separate the velocity data from one register into the two registers used by the driver.
   // The first rung divides the original value by 1000 to calculate the Most Significant Word.  The Programmed_Speed must be in DINT format and tag command_data_block[4] must be in INT format.  Using these formats results in a truncated, not rounded, value.
   6: DIV(Programmed_Speed,1000,command_data_block[4]);
   // Multiply the result of the above divide operation by 1000.  This intermediate operation will be used to calculate the Least Significant Word of the separated value.   Tag upper_result_X_1000 has the DINT data type.
   7: MUL(command_data_block[4],1000,Upper_Result_X_1000);
   // Subtract intermediate value upper_result_X_1000 from the original value to get the Least Significant Word value.
   // The Least_Significant_Word tag has an INT format and the result of the operation will have a range of -999 to 999.
   8: SUB(Programmed_Speed,Upper_Result_X_1000,command_data_block[5]);
   // Move the acceleration value from outside the AOI instruction to word six of the ten word command block.
   9: MOV(Acceleration,command_data_block[6]);
   // Move the deceleration value from outside the AOI instruction to word seven of the ten word command block.
   10: MOV(Deceleration,command_data_block[7]);
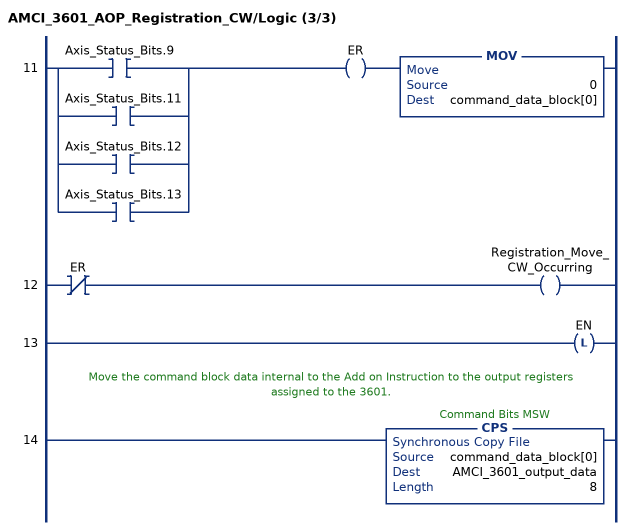
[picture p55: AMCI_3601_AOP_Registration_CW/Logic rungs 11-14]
   11: [XIC(Axis_Status_Bits.9) ,XIC(Axis_Status_Bits.11) ,XIC(Axis_Status_Bits.12) ,XIC(Axis_Status_Bits.13) ]OTE(ER)MOV(0,command_data_block[0]);
   12: XIO(ER)OTE(Registration_Move_CW_Occurring);
   13: OTL(EN);
   // Move the command block data internal to the Add on Instruction to the output registers assigned to the 3601.
   14: CPS(command_data_block[0],AMCI_3601_output_data,8);
END_ROUTINE
END_ADD_ON_INSTRUCTION
